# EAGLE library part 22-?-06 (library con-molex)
CONNECTOR wire to board 2.54 mm (.1 inch) pitch header
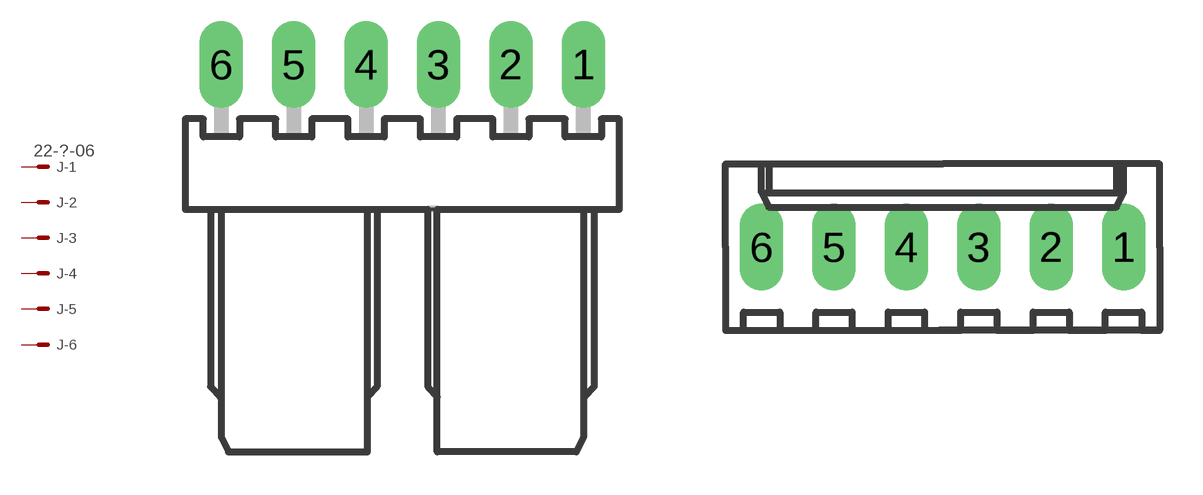
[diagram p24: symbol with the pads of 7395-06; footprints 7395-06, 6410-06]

Designator prefix J; gates -1=MV -2=M -3=M -4=M -5=M -6=M

## 22-05-7068-06 (OC_FARNELL: unknown; OC_NEWARK: unknown)  [7395-06]
1  -1:S  pas
2  -2:S  pas
3  -3:S  pas
4  -4:S  pas
5  -5:S  pas
6  -6:S  pas

## 22-27-2061-06 (OC_FARNELL: unknown; OC_NEWARK: unknown)  [6410-06]
Pads as for 7395-06

## Footprint 7395-06 (pad centres in mm)
MOLEX 2.54mm KK RA CONNECTOR Fixed Orientation
drill 1.016 long: 1 6.35,0; 2 3.81,0; 3 1.27,0; 4 -1.27,0; 5 -3.81,0; 6 -6.35,0

## Footprint 6410-06 (pad centres in mm)
MOLEX 2.54mm KK CONNECTOR
drill 1.016 long: 1 6.35,0; 2 3.81,0; 3 1.27,0; 4 -1.27,0; 5 -3.81,0; 6 -6.35,0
